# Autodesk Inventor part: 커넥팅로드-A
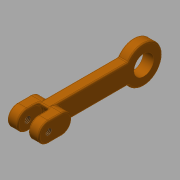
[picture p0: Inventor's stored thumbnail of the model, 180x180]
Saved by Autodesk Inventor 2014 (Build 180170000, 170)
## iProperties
Created: 2018-01
Part Number: 커넥팅로드-A
Material: 알루미늄 6061
Document SubType Name: Modeling
Designer: mduedu
Density: 1 g/cm^3
Appearance: 주황색
Author: mduedu
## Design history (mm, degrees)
sketch "스케치1"
  geometry: L1 (0, 0)-(0, 40); L2 (3.75, 40)-(3.75, 5.911); L3 (-3.75, 40)-(-3.75, 5.911); A1 r 7 centre (0, 0) between (3.75, 5.911) and (-3.75, 5.911); A2 r 3.75 centre (0, 40) between (3.75, 40) and (-3.75, 40); 1 further point
  constraints: 6 end point, 4 point on circle, 2 centre point, 2 coincident, 2 parallel, 2 tangent, 1 vertical
  dimensions: "d1" = 40 distance of L1.start L1.end; "d2" = 7.5 diameter of A2; "d3" = 14 diameter of A1
extrude "돌출1" new body sketch "스케치1" stored distance "d4" = 4; taper "d5" = 0 deg
sketch "스케치2"
  geometry: L1 (-3.75, 40)-(-3.75, 35); L2 (3.75, 40)-(3.75, 35); A1 r 3.75 centre (0, 40) between (3.75, 40) and (-3.75, 40) reference; A2 r 3.75 centre (0, 40) between (3.75, 40) and (-3.75, 40); A3 r 3.75 centre (0, 35) between (-3.75, 35) and (3.75, 35); 1 further point
  constraints: 4 end point, 4 point on circle, 2 centre point, 2 tangent, 1 coincident, 1 equal radius, 1 point on line, 1 vertical alignment
  dimensions: "d6" = 5 distance of A3.centre A1.centre
extrude "돌출2" join sketch "스케치2" stored distance "d7" = 12; taper "d8" = 0 deg
sketch "스케치3"
  geometry: L1 (3.75, 40)-(3.75, 38); L2 (-3.75, 40)-(-3.75, 38); A1 r 3.75 centre (0, 40) between (3.75, 40) and (-3.75, 40) reference; A2 r 3.75 centre (0, 40) between (3.75, 40) and (-3.75, 40); A3 r 3.75 centre (0, 38) between (-3.75, 38) and (3.75, 38); 1 further point
  constraints: 4 end point, 4 point on circle, 3 tangent, 2 centre point, 1 coincident, 1 equal radius, 1 parallel, 1 point on line
  dimensions: "d9" = 2 distance of A3.centre A1.centre
extrude "돌출3" cut sketch "스케치3" stored distance "d10" = 4; taper "d11" = 0 deg
fillet "모깎기5" dims "d16" = 0.5
fillet "모깎기6" dims "d17" = 0.5
fillet "모깎기7" dims "d18" = 0.5
fillet "모깎기8" dims "d19" = 0.5
hole "구멍1" diameter "d22" = 7.5; stored, may be unused: countersink angle "d26" = 90 deg, drill point angle "d28" = 118 deg; dims "d20" = 10, "d21" = 10, "d23" = 6, "d24" = 4, "d25" = 2, "d27" = 8
sketch "스케치4"
  geometry: A1 r 3.75 centre (40, 0) between (40, -3.75) and (40, 3.75) reference; 2 further points
  constraints: 1 coincident
sketch "스케치5"
  geometry: 1 further point
  constraints: 1 other
hole "구멍2" sketch "스케치5" at (40, 0) diameter "d29" = 2.459; stored, may be unused: countersink angle "d33" = 90 deg, drill point angle "d35" = 0 deg; dims "d30" = 6, "d31" = 4, "d32" = 2, "d34" = 8
sketch "스케치6"
  geometry: 1 further point
  constraints: 1 other
hole "구멍4" sketch "스케치6" at (-40, 0) diameter "d36" = 2.459; stored, may be unused: countersink angle "d40" = 90 deg, drill point angle "d42" = 0 deg; dims "d37" = 6, "d38" = 4, "d39" = 2, "d41" = 8
node "솔리드1"
